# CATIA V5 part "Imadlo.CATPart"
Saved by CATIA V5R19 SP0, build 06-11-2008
Part number: Korpus
Bounding box of the stored display mesh (mm): x -53.901 to 594.099, y -23 to 142, z 0 to 154
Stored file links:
  G:\Catia\CD\Ustawienia\Imadlo\Imadlo.CATPart
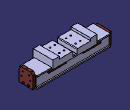
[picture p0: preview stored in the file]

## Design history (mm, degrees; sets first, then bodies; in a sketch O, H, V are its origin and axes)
Parameters
  Rozstaw = 35 mm
Body1 (main body)
  Sketch1 on xy-plane, origin (0, 0, 0), H (1, 0, 0), V (0, 1, 0)
    line L1 (-33.9007, 122) -> (571.0993, 122)
    line L2 (571.0993, 122) -> (571.0993, 0)
    line L3 (571.0993, 0) -> (-33.9007, 0)
    line L4 (-33.9007, 0) -> (-33.9007, 122)
    point P3 (571.0993, 0)
    length L1 = 605
    length L4 = 122
    horizontal: L1 H, L3 H
    vertical: L2 V, L4 V
    coincidence: P3 H
  Pad1: profile Sketch1, direction (0, 0, 1), length 96
  Sketch2 on face of Pad1 from Sketch1.L2, origin (571.0993, 0, 0), H (0, 1, 0), V (0, 0, 1)
    reference projected line E1 (122, 0) -> (122, 96) from edge [face of Pad1 from Sketch1.L1 | face of Pad1 from Sketch1.L2]
    reference projected line E2 (0, 0) -> (0, 96) from edge [face of Pad1 from Sketch1.L2 | face of Pad1 from Sketch1.L3]
    line L1 (-10, 10) -> (132, 10)
    line L2 (132, 10) -> (132, 0)
    line L3 (132, 0) -> (-10, 0)
    line L4 (-10, 0) -> (-10, 10)
    point P3 (132, 0)
    reference projected line E3 (0, 0) -> (0, 96) from edge [face of Pad1 from Sketch1.L2 | face of Pad1 from Sketch1.L3]
    point P5 (0, 63.7983)
    construction line L5 through (0, 63.7983) direction (1, 0)
    construction line L6 through (0, 63.7983) direction (0, 1)
    line L7 (-10, 96) -> (132, 96)
    line L8 (132, 96) -> (132, 86)
    line L9 (132, 86) -> (-10, 86)
    line L10 (-10, 86) -> (-10, 96)
    reference projected line E4 (0, 96) -> (122, 96) from edge [face of Pad1 from Sketch1.L2 | end face of Pad1]
    reference projected line E5 (122, 0) -> (122, 96) from edge [face of Pad1 from Sketch1.L1 | face of Pad1 from Sketch1.L2]
    distance E1 E2 = 122 (reference)
    length L3 = 142
    distance E3 L4 = 10
    length L2 = 10
    distance L8 E5 = 10
    horizontal: L1 H, L3 H
    vertical: L2 V, L4 V
    coincidence: P3 H, L7 E4
  Pad2: profile Sketch2, direction (-1, 0, 0), length 605
Body2
  Sketch3 on face of Pad2, origin (571.0993, 0, 0), H (0, 1, 0), V (0, 0, 1)
    axis line L1 (61, 143.9611) -> (61, -19.6263)
    reference projected line E1 (0, 0) -> (0, 96) from edge [face of Pad2 | face of Pad1 from Sketch1.L3]
    reference projected line E2 (122, 0) -> (122, 96) from edge [face of Pad1 from Sketch1.L1 | face of Pad2]
    point P3 (61, 0)
    line L2 (61, 0) -> (116.5725, 0)
    point P4 (116.5725, 0)
    line L3 (116.5725, 0) -> (116.5725, 97.641)
    point P5 (116.5725, 97.641)
    line L4 (116.5725, 97.641) -> (100.7654, 118.2271)
    point P6 (100.7654, 118.2271)
    line L5 (100.7654, 118.2271) -> (61, 118.2271)
    point P7 (61, 118.2271)
    point P8 (61, 0)
    point P9 (5.4275, 0)
    point P10 (5.4275, 97.641)
    point P11 (21.2346, 118.2271)
    point P12 (61, 118.2271)
    line L6 (61, 0) -> (5.4275, 0)
    line L7 (5.4275, 0) -> (5.4275, 97.641)
    line L8 (5.4275, 97.641) -> (21.2346, 118.2271)
    line L9 (21.2346, 118.2271) -> (61, 118.2271)
    distance L1 E2 = 61
    parallelism: E1 L1
    coincidence: P3 L1, P3 H, P7 L1, P3 P8, P7 P12
    horizontal: L2 H, L5 H
    vertical: L3 V
    symmetry: P3 P8 L1, P4 P9 L1, P5 P10 L1, P6 P11 L1, P7 P12 L1, L2 L6 L1, L3 L7 L1, L4 L8 L1, L5 L9 L1
  Pad3: profile Sketch3, direction (1, 0, 0), length 20
  Sketch4 on end face of Pad3, origin (591.0993, 0, 0), H (0, 1, 0), V (0, 0, 1)
    axis line L1 (60.5725, 124.7527) -> (60.5725, -6.2024)
    reference projected line E1 (116.5725, 0) -> (116.5725, 97.641) from edge [face of Pad3 from Sketch3.L3 | end face of Pad3]
    circle A1 centre (87.4382, 87.6073) radius 5
    circle A2 centre (96.8892, 53.0444) radius 5
    circle A3 centre (33.7069, 87.6073) radius 5
    circle A4 centre (24.2559, 53.0444) radius 5
    distance E1 L1 = 56
    radius A1 = 5
    radius A2 = 5
    vertical: L1 V
    symmetry: A1 A3 L1, A2 A4 L1
  Pocket1: profile Sketch4, direction (-1, 0, 0), length 5
  Sketch5 on end face of Pocket1, origin (586.0993, 0, 0), H (0, 1, 0), V (0, 0, 1)
    point P1 (87.3487, 87.8507)
    point P2 (87.5408, 83.9222)
    point P3 (90.847, 86.0528)
    point P4 (90.6549, 89.9813)
    point P5 (87.1566, 91.7792)
    point P6 (83.8505, 89.6486)
    point P7 (84.0426, 85.7201)
    point P8 (89.1939, 84.9875)
    line L1 (87.5408, 83.9222) -> (90.847, 86.0528)
    line L2 (90.847, 86.0528) -> (90.6549, 89.9813)
    line L3 (90.6549, 89.9813) -> (87.1566, 91.7792)
    line L4 (87.1566, 91.7792) -> (83.8505, 89.6486)
    line L5 (83.8505, 89.6486) -> (84.0426, 85.7201)
    line L6 (84.0426, 85.7201) -> (87.5408, 83.9222)
    construction line L7 (87.3487, 87.8507) -> (89.1939, 84.9875)
    construction circle A1 centre (87.3487, 87.8507) radius 3.9332
    construction arc A2 centre (83.8505, 89.6486) radius 3.9332 from (87.1566, 91.7792) to (84.0426, 85.7201) cw
    construction arc A3 centre (90.847, 86.0528) radius 3.9332 from (90.6549, 89.9813) to (87.5408, 83.9222) ccw
    point P9 (97.0752, 49.069)
    construction circle A4 centre (96.8831, 52.9975) radius 3.9332
    point P10 (100.3814, 51.1996)
    point P11 (100.1893, 55.1281)
    point P12 (96.691, 56.926)
    point P13 (93.3849, 54.7953)
    point P14 (93.577, 50.8668)
    point P15 (96.8831, 52.9975)
    construction arc A5 centre (93.3849, 54.7953) radius 3.9332 from (96.691, 56.926) to (93.577, 50.8668) cw
    construction arc A6 centre (100.3814, 51.1996) radius 3.9332 from (100.1893, 55.1281) to (97.0752, 49.069) ccw
    line L8 (97.0752, 49.069) -> (100.3814, 51.1996)
    point P16 (98.7283, 50.1343)
    line L9 (96.691, 56.926) -> (93.3849, 54.7953)
    construction line L10 (96.8831, 52.9975) -> (98.7283, 50.1343)
    line L11 (100.3814, 51.1996) -> (100.1893, 55.1281)
    line L12 (100.1893, 55.1281) -> (96.691, 56.926)
    line L13 (93.3849, 54.7953) -> (93.577, 50.8668)
    line L14 (93.577, 50.8668) -> (97.0752, 49.069)
    point P17 (37.3033, 88.6209)
    construction circle A7 centre (33.4938, 87.6422) radius 3.9332
    point P18 (34.5509, 91.4306)
    point P19 (30.7415, 90.4519)
    point P20 (29.6843, 86.6635)
    point P21 (32.4366, 83.8537)
    point P22 (36.2461, 84.8324)
    point P23 (33.4938, 87.6422)
    construction arc A8 centre (32.4366, 83.8537) radius 3.9332 from (29.6843, 86.6635) to (36.2461, 84.8324) cw
    construction arc A9 centre (34.5509, 91.4306) radius 3.9332 from (30.7415, 90.4519) to (37.3033, 88.6209) ccw
    line L15 (37.3033, 88.6209) -> (34.5509, 91.4306)
    point P24 (35.9271, 90.0258)
    line L16 (29.6843, 86.6635) -> (32.4366, 83.8537)
    construction line L17 (33.4938, 87.6422) -> (35.9271, 90.0258)
    line L18 (34.5509, 91.4306) -> (30.7415, 90.4519)
    line L19 (30.7415, 90.4519) -> (29.6843, 86.6635)
    line L20 (32.4366, 83.8537) -> (36.2461, 84.8324)
    line L21 (36.2461, 84.8324) -> (37.3033, 88.6209)
    point P25 (24.2065, 49.1817)
    construction circle A10 centre (24.0144, 53.1102) radius 3.9332
    point P26 (27.5126, 51.3123)
    point P27 (27.3205, 55.2408)
    point P28 (23.8223, 57.0387)
    point P29 (20.5162, 54.9081)
    point P30 (20.7083, 50.9796)
    point P31 (24.0144, 53.1102)
    construction arc A11 centre (20.5162, 54.9081) radius 3.9332 from (23.8223, 57.0387) to (20.7083, 50.9796) cw
    construction arc A12 centre (27.5126, 51.3123) radius 3.9332 from (27.3205, 55.2408) to (24.2065, 49.1817) ccw
    line L22 (24.2065, 49.1817) -> (27.5126, 51.3123)
    point P32 (25.8596, 50.247)
    line L23 (23.8223, 57.0387) -> (20.5162, 54.9081)
    construction line L24 (24.0144, 53.1102) -> (25.8596, 50.247)
    line L25 (27.5126, 51.3123) -> (27.3205, 55.2408)
    line L26 (27.3205, 55.2408) -> (23.8223, 57.0387)
    line L27 (20.5162, 54.9081) -> (20.7083, 50.9796)
    line L28 (20.7083, 50.9796) -> (24.2065, 49.1817)
    coincidence: A1 P2, A1 P3, A1 P4, A1 P5, A1 P6, A1 P7, A2 P1, A3 P1, A4 P9, A4 P10, A4 P11, A4 P12, A4 P13, A4 P14, A5 P15, A6 P15, A7 P17, A7 P18, A7 P19, A7 P20, A7 P21, A7 P22, A8 P23, A9 P23, A10 P25, A10 P26, A10 P27, A10 P28, A10 P29, A10 P30, A11 P31, A12 P31
    midpoint: P8 L1, P16 L8, P24 L15, P32 L22
    parallelism: L1 L4, L8 L9, L15 L16, L22 L23
  Pad4: profile Sketch5, direction (1, 0, 0), length 3
  Sketch6 on end face of Pad3, origin (591.0993, 0, 0), H (0, 1, 0), V (0, 0, 1)
    axis line L1 (60.5725, 130.0253) -> (60.5725, -9.7987)
    reference projected line E1 (116.5725, 0) -> (116.5725, 97.641) from edge [face of Pad3 from Sketch3.L3 | end face of Pad3]
    circle A1 centre (80.8065, 12.4339) radius 8
    circle A2 centre (40.3386, 12.4339) radius 8
    distance E1 L1 = 56
    radius A1 = 8
    vertical: L1 V
    symmetry: A1 A2 L1
  Pad5: profile Sketch6, direction (1, 0, 0), length 3
  Sketch7 on face of Pad2, origin (-33.9007, 0, 0), H (0, -1, 0), V (0, 0, 1)
    line L1 (-117, 93.7494) -> (-5, 93.7494)
    line L2 (-5, 93.7494) -> (-5, 0)
    line L3 (-5, 0) -> (-117, 0)
    line L4 (-117, 0) -> (-117, 93.7494)
    point P3 (-5, 0)
    reference projected line E1 (-122, 0) -> (-122, 96) from edge [face of Pad2 | face of Pad1 from Sketch1.L1]
    distance L4 L2 = 112
    distance L4 E1 = 5
    horizontal: L1 H, L3 H
    vertical: L2 V, L4 V
    coincidence: P3 H
  Pad6: profile Sketch7, direction (-1, 0, 0), length 20
  Sketch8 on end face of Pad6, origin (-53.9007, 0, 0), H (0, -1, 0), V (0, 0, 1)
    axis line L1 (-61, 98.9991) -> (-61, -4.9159)
    reference projected line E1 (-5, 0) -> (-5, 93.7494) from edge [face of Pad6 from Sketch7.L2 | end face of Pad6]
    circle A1 centre (-30.922, 74.1861) radius 5
    circle A2 centre (-28.0456, 27.8037) radius 5
    circle A3 centre (-91.078, 74.1861) radius 5
    circle A4 centre (-93.9544, 27.8037) radius 5
    distance E1 L1 = 56
    radius A2 = 5
    radius A1 = 5
    vertical: L1 V
    symmetry: A1 A3 L1, A2 A4 L1
  Pocket2: profile Sketch8, direction (1, 0, 0), length 5
  Sketch9 on end face of Pocket2, origin (-48.9007, 0, 0), H (0, -1, 0), V (0, 0, 1)
    point P1 (-31.1153, 74.1426)
    point P2 (-30.7259, 70.3813)
    point P3 (-27.6632, 72.5991)
    point P4 (-28.0525, 76.3605)
    point P5 (-31.5046, 77.904)
    point P6 (-34.5674, 75.6861)
    point P7 (-34.178, 71.9248)
    point P8 (-29.1946, 71.4902)
    line L1 (-30.7259, 70.3813) -> (-27.6632, 72.5991)
    line L2 (-27.6632, 72.5991) -> (-28.0525, 76.3605)
    line L3 (-28.0525, 76.3605) -> (-31.5046, 77.904)
    line L4 (-31.5046, 77.904) -> (-34.5674, 75.6861)
    line L5 (-34.5674, 75.6861) -> (-34.178, 71.9248)
    line L6 (-34.178, 71.9248) -> (-30.7259, 70.3813)
    construction line L7 (-31.1153, 74.1426) -> (-29.1946, 71.4902)
    construction circle A1 centre (-31.1153, 74.1426) radius 3.7814
    construction arc A2 centre (-34.5674, 75.6861) radius 3.7814 from (-31.5046, 77.904) to (-34.178, 71.9248) cw
    construction arc A3 centre (-27.6632, 72.5991) radius 3.7814 from (-28.0525, 76.3605) to (-30.7259, 70.3813) ccw
    line L8 (-27.7382, 24.0475) -> (-24.6754, 26.2654)
    line L9 (-24.6754, 26.2654) -> (-25.0648, 30.0267)
    line L10 (-25.0648, 30.0267) -> (-28.5169, 31.5702)
    line L11 (-28.5169, 31.5702) -> (-31.5796, 29.3524)
    line L12 (-31.5796, 29.3524) -> (-31.1903, 25.591)
    line L13 (-31.1903, 25.591) -> (-27.7382, 24.0475)
    construction circle A4 centre (-28.1275, 27.8089) radius 3.7814
    line L14 (-93.6169, 23.9855) -> (-90.5541, 26.2034)
    line L15 (-90.5541, 26.2034) -> (-90.9435, 29.9647)
    line L16 (-90.9435, 29.9647) -> (-94.3956, 31.5082)
    line L17 (-94.3956, 31.5082) -> (-97.4583, 29.2904)
    line L18 (-97.4583, 29.2904) -> (-97.069, 25.529)
    line L19 (-97.069, 25.529) -> (-93.6169, 23.9855)
    construction circle A5 centre (-94.0062, 27.7469) radius 3.7814
    line L20 (-90.873, 70.3378) -> (-87.8103, 72.5556)
    line L21 (-87.8103, 72.5556) -> (-88.1996, 76.317)
    line L22 (-88.1996, 76.317) -> (-91.6517, 77.8605)
    line L23 (-91.6517, 77.8605) -> (-94.7144, 75.6426)
    line L24 (-94.7144, 75.6426) -> (-94.3251, 71.8813)
    line L25 (-94.3251, 71.8813) -> (-90.873, 70.3378)
    construction circle A6 centre (-91.2623, 74.0991) radius 3.7814
    coincidence: A1 P2, A1 P3, A1 P4, A1 P5, A1 P6, A1 P7, A2 P1, A3 P1
    midpoint: P8 L1
    parallelism: L1 L4
  Pad7: profile Sketch9, direction (-1, 0, 0), length 3
Body3
  Sketch10 on face of Pad2, origin (0, 0, 96), H (1, 0, 0), V (0, 1, 0)
    line L1 (286.0993, 142) -> (451.0993, 142)
    line L2 (451.0993, 142) -> (451.0993, -20)
    line L3 (451.0993, -20) -> (286.0993, -20)
    line L4 (286.0993, -20) -> (286.0993, 142)
    reference projected line E1 (571.0993, -10) -> (-33.9007, -10) from edge [face of Pad2 from Sketch2.L7 | face of Pad2 from Sketch2.L10]
    reference projected line E2 (-33.9007, 122) -> (-33.9007, 0) from edge [face of Pad2 | face of Pad2]
    distance L3 L1 = 162
    distance E1 L3 = 10
    length L1 = 165
    distance L4 E2 = 320 {= Rozstaw/2+302.5mm}
    horizontal: L1 H, L3 H
    vertical: L2 V, L4 V
  Pad8: profile Sketch10, direction (0, 0, 1), length 58
  Sketch11 on face of Pad8 from Sketch10.L2, origin (451.0993, 0, 0), H (0, 1, 0), V (0, 0, 1)
    line L1 (132, 96) -> (142, 96)
    line L2 (142, 96) -> (142, 86)
    line L3 (142, 86) -> (132, 86)
    line L4 (132, 86) -> (132, 96)
    reference projected line E1 (132, 86) -> (132, 96) from edge [face of Pad2 from Sketch2.L8 | start face of Pad2]
    reference projected line E2 (-20, 96) -> (142, 96) from edge [start face of Pad8 | face of Pad8 from Sketch10.L2]
    line L5 (-20, 96.0989) -> (-10, 96.0989)
    line L6 (-10, 96.0989) -> (-10, 86.0989)
    line L7 (-10, 86.0989) -> (-20, 86.0989)
    line L8 (-20, 86.0989) -> (-20, 96.0989)
    reference projected line E3 (-10, 96) -> (-10, 86) from edge [face of Pad2 from Sketch2.L10 | start face of Pad2]
    length L3 = 10
    length L2 = 10
    horizontal: L1 H, L3 H
    vertical: L2 V, L4 V
    coincidence: L4 E1, L1 E2, L6 E3
  Pad9: profile Sketch11, direction (-1, 0, 0), length 215
  Sketch12 on end face of Pad8, origin (0, 0, 154), H (1, 0, 0), V (0, 1, 0)
    line L1 (286.0993, 184.4682) -> (398.0993, 184.4682)
    line L2 (398.0993, 184.4682) -> (398.0993, -56.376)
    line L3 (398.0993, -56.376) -> (286.0993, -56.376)
    line L4 (286.0993, -56.376) -> (286.0993, 184.4682)
    reference projected line E1 (286.0993, 142) -> (286.0993, -20) from edge [face of Pad9 | end face of Pad8]
    length L1 = 112
    horizontal: L1 H, L3 H
    vertical: L2 V, L4 V
    coincidence: E1 L4
  Pocket3: profile Sketch12, direction (0, 0, -1), length 20
  Sketch13 on end face of Pocket3, origin (0, 0, 134), H (1, 0, 0), V (0, 1, 0)
    axis line L1 (299.723, 61) -> (606.2907, 61)
    reference projected line E1 (322.3084, -20) -> (507.3084, -20) from edge [face of Pad9 | end face of Pocket3]
    construction line L2 (316.0993, 99) -> (354.0993, 99)
    construction line L3 (354.0993, 99) -> (354.0993, 23)
    construction line L4 (354.0993, 23) -> (316.0993, 23)
    construction line L5 (316.0993, 23) -> (316.0993, 99)
    circle A1 centre (316.0993, 99) radius 6
    circle A2 centre (354.0993, 99) radius 6
    point P7 (413.52, 95.2851)
    circle A3 centre (354.0993, 23) radius 6
    circle A4 centre (316.0993, 23) radius 6
    point P8 (370.8084, 17)
    reference projected line E2 (286.0993, 142) -> (286.0993, -20) from edge [face of Pad9 | end face of Pocket3]
    distance L1 E1 = 81
    length L5 = 76
    length L4 = 38
    distance L2 L1 = 38
    radius A1 = 6
    radius A2 = 6
    radius A3 = 6
    radius A4 = 6
    distance L5 E2 = 30
    perpendicularity: L3 L4, L2 L3
  Pocket4: profile Sketch13, direction (0, 0, -1), length 20
  Chamfer1: length 5, angle 45, on edge [face of Pad9 | end face of Pocket3]
  Plane1: type Offset, Offset 302.5, RefPlane face of Pad2
  Mirror1: of the body so far, about Plane1
Body4
  Sketch14 on face of Pad9 from Sketch11.L7, origin (0, 0, 86.0989), H (1, 0, 0), V (0, -1, 0)
    point P1 (336.9499, 20)
    line L1 (336.9499, 20) -> (483.6804, 20)
    line L2 (483.6804, 20) -> (483.6804, 0)
    line L3 (483.6804, 0) -> (336.9499, 0)
    line L4 (336.9499, 0) -> (336.9499, 20)
    point P2 (483.6804, 20)
    point P3 (483.6804, 0)
    point P4 (336.9499, 0)
    reference projected line E1 (518.5993, 20) -> (303.5993, 20) from edge [face of Pad9 | face of Pad9 from Sketch11.L7]
    axis line L5 (609.8523, -61) -> (176.2805, -61)
    reference projected line E2 (571.0993, -132) -> (-33.9007, -132) from edge [face of Pad2 from Sketch2.L3 | face of Pad2 from Sketch2.L2]
    point P7 (336.9499, -142)
    point P8 (483.6804, -142)
    point P9 (483.6804, -122)
    point P10 (336.9499, -122)
    line L6 (336.9499, -142) -> (483.6804, -142)
    line L7 (483.6804, -142) -> (483.6804, -122)
    line L8 (483.6804, -122) -> (336.9499, -122)
    line L9 (336.9499, -122) -> (336.9499, -142)
    reference intersected line E3 through (268.5993, 0) direction (0, 1) from Plane1
    point P13 (200.2486, 20)
    point P14 (53.5182, 20)
    point P15 (53.5182, 0)
    point P16 (200.2486, 0)
    point P17 (200.2486, -142)
    point P18 (53.5182, -142)
    point P19 (53.5182, -122)
    point P20 (200.2486, -122)
    line L10 (200.2486, 20) -> (53.5182, 20)
    line L11 (53.5182, 20) -> (53.5182, 0)
    line L12 (53.5182, 0) -> (200.2486, 0)
    line L13 (200.2486, 0) -> (200.2486, 20)
    line L14 (200.2486, -142) -> (53.5182, -142)
    line L15 (53.5182, -142) -> (53.5182, -122)
    line L16 (53.5182, -122) -> (200.2486, -122)
    line L17 (200.2486, -122) -> (200.2486, -142)
    length L2 = 20
    distance L5 E2 = 71
    horizontal: L1 H, L3 H, L5 H
    vertical: L2 V, L4 V
    coincidence: L1 E1
    symmetry: P1 P7 L5, P2 P8 L5, P3 P9 L5, P4 P10 L5, L1 L6 L5, L2 L7 L5, L3 L8 L5, L4 L9 L5, P1 P13 E3, P2 P14 E3, P3 P15 E3, P4 P16 E3, P7 P17 E3, P8 P18 E3, P9 P19 E3, P10 P20 E3, L1 L10 E3, L2 L11 E3, L3 L12 E3, L4 L13 E3, L6 L14 E3, L7 L15 E3, L8 L16 E3, L9 L17 E3
  Pad10: profile Sketch14, direction (0, 0, -1), length 10
  Sketch15 on end face of Pad10, origin (0, 0, 76.0989), H (1, 0, 0), V (0, -1, 0)
    circle A1 centre (361.4265, 10) radius 5
    point P1 (361.4265, 10)
    circle A2 centre (438.2674, 10) radius 5
    point P2 (438.2674, 10)
    reference projected line E1 (571.0993, 10) -> (-33.9007, 10) from edge [face of Pad2 from Sketch2.L4 | face of Pad2 from Sketch2.L3]
    reference projected line E2 (571.0993, 10) -> (-33.9007, 10) from edge [face of Pad2 from Sketch2.L4 | face of Pad2 from Sketch2.L3]
    axis line L1 (596.9847, -61) -> (314.3838, -61)
    reference projected line E3 (571.0993, -132) -> (-33.9007, -132) from edge [face of Pad2 from Sketch2.L3 | face of Pad2 from Sketch2.L2]
    circle A3 centre (438.2674, -132) radius 5
    circle A4 centre (361.4265, -132) radius 5
    reference intersected line E4 through (268.5993, 0) direction (0, 1) from Plane1
    circle A5 centre (175.7721, 10) radius 5
    circle A6 centre (98.9312, 10) radius 5
    circle A7 centre (98.9312, -132) radius 5
    circle A8 centre (175.7721, -132) radius 5
    radius A2 = 5
    radius A1 = 5
    distance L1 E3 = 71
    coincidence: P2 E1, P1 E2
    symmetry: A2 A3 L1, A1 A4 L1, A1 A5 E4, A2 A6 E4, A3 A7 E4, A4 A8 E4
  Pocket5: profile Sketch15, direction (0, 0, 1), length 3
Body5
  Sketch16 on face of Pad1 from Sketch1.L3, origin (0, 0, 0), H (1, 0, 0), V (0, 0, 1)
    circle A1 centre (268.5993, 48.5265) radius 21.1599
    point P1 (268.5993, 48.5265)
    reference intersected line E1 through (268.5993, 0) direction (0, 1) from Plane1
    distance P1 E1 = 0
  Pad11: profile Sketch16, direction (0, -1, 0), length 3
  Sketch17 on end face of Pad11, origin (0, -3, 0), H (1, 0, 0), V (0, 0, 1)
    circle A1 centre (268.5993, 48.5265) radius 15.6012
    reference projected circle E1 centre (268.5993, 48.5265) radius 21.1599 from edge [face of Pad11 from Sketch16.A1 | end face of Pad11]
    concentricity: E1 A1
  Pad12: profile Sketch17, direction (0, -1, 0), length 20
  Sketch18 on end face of Pad12, origin (0, -23, 0), H (1, 0, 0), V (0, 0, 1)
    point P1 (268.7117, 49.0181)
    point P2 (272.611, 37.4753)
    point P3 (280.6578, 46.6237)
    point P4 (276.7584, 58.1665)
    point P5 (264.8123, 60.561)
    point P6 (256.7656, 51.4126)
    point P7 (260.665, 39.8697)
    point P8 (276.6344, 42.0495)
    line L1 (272.611, 37.4753) -> (280.6578, 46.6237)
    line L2 (280.6578, 46.6237) -> (276.7584, 58.1665)
    line L3 (276.7584, 58.1665) -> (264.8123, 60.561)
    line L4 (264.8123, 60.561) -> (256.7656, 51.4126)
    line L5 (256.7656, 51.4126) -> (260.665, 39.8697)
    line L6 (260.665, 39.8697) -> (272.611, 37.4753)
    construction line L7 (268.7117, 49.0181) -> (276.6344, 42.0495)
    construction circle A1 centre (268.7117, 49.0181) radius 12.1837
    construction arc A2 centre (256.7656, 51.4126) radius 12.1837 from (264.8123, 60.561) to (260.665, 39.8697) cw
    construction arc A3 centre (280.6578, 46.6237) radius 12.1837 from (276.7584, 58.1665) to (272.611, 37.4753) ccw
    coincidence: A1 P2, A1 P3, A1 P4, A1 P5, A1 P6, A1 P7, A2 P1, A3 P1
    midpoint: P8 L1
    parallelism: L1 L4
  Pocket6: profile Sketch18, direction (0, 1, 0), length 10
